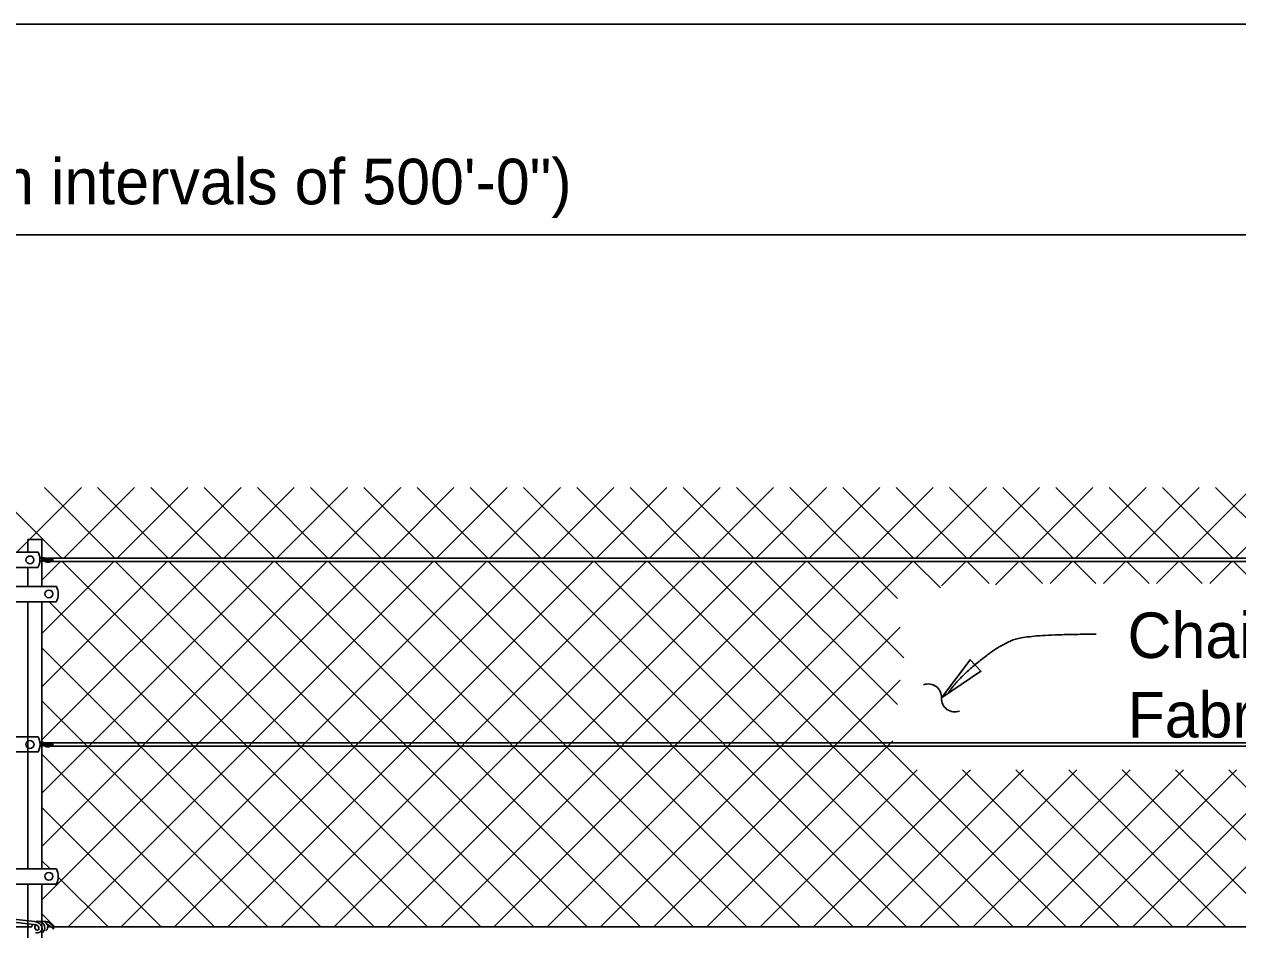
# Model space of a CAD drawing. Extents: x 0 to 41.1, y 0 to 26.4.
# Drawn here: x 12.4 to 17.77, y 22.39 to 26.4 of the extents above; entities that cross this region are included whole.
import ezdxf

# ---------------------------------------------------------------- set-up
doc = ezdxf.new("R2010")
doc.units = 0
for name, color, linetype in [('Dimension', 7, 'Continuous'), ('Miscellaneous', 7, 'Continuous'), ('Miscellaneous1', 7, 'Continuous'), ('SteelMisc', 7, 'Continuous'), ('TextStructures', 7, 'Continuous')]:
    doc.layers.add(name, color=color, linetype=linetype)

msp = doc.modelspace()

# ---------------------------------------------------------------- linework, layer by layer
at = {"layer": 'Dimension'}
msp.add_line((2.2062, 25.4682), (22.2062, 25.4682), dxfattribs=at)
msp.add_lwpolyline([(16.4595, 23.4182), (16.6347, 23.5361), (16.5861, 23.5872)], close=True, dxfattribs=at)
for centre, start, end in [((16.4004, 23.4201), 357.7178, 109.445), ((16.5195, 23.4153), 177.7178, 289.445)]:
    msp.add_arc(centre, 0.0596, start, end, dxfattribs=at)
msp.add_open_spline([(17.1447, 23.6998), (16.8545, 23.6998), (16.7179, 23.655), (16.5309, 23.5014), (16.4925, 23.4438)], degree=2, dxfattribs=at)
at = {"layer": 'Miscellaneous'}
for p, q in [((12.3656, 24.0631), (12.6516, 24.349)), ((12.4881, 24.349), (12.8006, 24.0365)), ((12.5748, 24.0365), (12.8873, 24.349)), ((12.7238, 24.349), (13.0364, 24.0365)), ((12.8105, 24.0365), (13.123, 24.349)), ((12.9595, 24.349), (13.2721, 24.0365)), ((13.0462, 24.0365), (13.3587, 24.349)), ((13.1952, 24.349), (13.5078, 24.0365)), ((13.2819, 24.0365), (13.5944, 24.349)), ((13.4309, 24.349), (13.7435, 24.0365)), ((13.5176, 24.0365), (13.8301, 24.349)), ((13.6666, 24.349), (13.9792, 24.0365)), ((13.7533, 24.0365), (14.0658, 24.349)), ((13.9023, 24.349), (14.2149, 24.0365)), ((13.989, 24.0365), (14.3015, 24.349)), ((14.138, 24.349), (14.4506, 24.0365)), ((14.2247, 24.0365), (14.5372, 24.349)), ((14.3737, 24.349), (14.6863, 24.0365)), ((14.4604, 24.0365), (14.7729, 24.349)), ((14.6094, 24.349), (14.922, 24.0365)), ((14.6961, 24.0365), (15.0086, 24.349)), ((14.8451, 24.349), (15.1577, 24.0365)), ((14.9318, 24.0365), (15.2443, 24.349)), ((15.0808, 24.349), (15.3934, 24.0365)), ((15.1675, 24.0365), (15.48, 24.349)), ((15.3165, 24.349), (15.6291, 24.0365)), ((15.4032, 24.0365), (15.7157, 24.349)), ((15.5522, 24.349), (15.8648, 24.0365)), ((15.6389, 24.0365), (15.9514, 24.349)), ((15.7879, 24.349), (16.1005, 24.0365)), ((15.8746, 24.0365), (16.1871, 24.349)), ((16.0236, 24.349), (16.3362, 24.0365)), ((16.1103, 24.0365), (16.4228, 24.349)), ((16.2593, 24.349), (16.5719, 24.0365)), ((16.346, 24.0365), (16.6585, 24.349)), ((16.4951, 24.349), (16.8076, 24.0365)), ((16.5817, 24.0365), (16.8942, 24.349)), ((16.7308, 24.349), (17.0433, 24.0365)), ((16.8174, 24.0365), (17.1299, 24.349)), ((16.9665, 24.349), (17.279, 24.0365)), ((17.0531, 24.0365), (17.3656, 24.349)), ((17.2022, 24.349), (17.5147, 24.0365)), ((17.2888, 24.0365), (17.6013, 24.349)), ((17.4379, 24.349), (17.7504, 24.0365)), ((17.5245, 24.0365), (17.837, 24.349)), ((17.6736, 24.349), (17.9861, 24.0365)), ((17.7602, 24.0365), (18.0727, 24.349)), ((12.352, 24.2494), (12.5649, 24.0365)), ((12.4771, 22.5246), (13.9742, 24.0218)), ((12.4771, 22.7603), (13.7385, 24.0218)), ((12.4771, 22.996), (13.5028, 24.0218)), ((12.4771, 23.2317), (13.2671, 24.0218)), ((12.4771, 23.4674), (13.0314, 24.0218)), ((12.4771, 23.7031), (12.7957, 24.0218)), ((12.4771, 23.9388), (12.56, 24.0218)), ((12.5669, 24.0218), (14.1839, 22.4048)), ((12.5929, 22.4048), (14.2099, 24.0218)), ((12.8026, 24.0218), (14.4196, 22.4048)), ((12.8286, 22.4048), (14.4456, 24.0218)), ((13.0383, 24.0218), (14.6553, 22.4048)), ((13.0643, 22.4048), (14.6813, 24.0218)), ((13.274, 24.0218), (14.891, 22.4048)), ((13.3, 22.4048), (14.917, 24.0218)), ((13.5097, 24.0218), (15.1267, 22.4048)), ((13.5357, 22.4048), (15.1527, 24.0218)), ((13.7454, 24.0218), (15.3624, 22.4048)), ((13.7714, 22.4048), (15.3884, 24.0218)), ((13.9811, 24.0218), (15.5981, 22.4048)), ((14.0071, 22.4048), (15.6241, 24.0218)), ((14.2168, 24.0218), (15.8338, 22.4048)), ((14.2428, 22.4048), (15.8598, 24.0218)), ((14.4525, 24.0218), (16.0695, 22.4048)), ((14.4785, 22.4048), (16.0955, 24.0218)), ((14.6882, 24.0218), (16.3052, 22.4048)), ((14.7142, 22.4048), (16.3312, 24.0218)), ((14.9239, 24.0218), (16.5409, 22.4048)), ((15.1596, 24.0218), (16.2441, 22.9373)), ((15.3953, 24.0218), (16.2441, 23.173)), ((15.631, 24.0218), (16.2647, 23.3881)), ((15.8667, 24.0218), (16.293, 23.5955)), ((16.1024, 24.0218), (16.2656, 23.8586)), ((16.3381, 24.0218), (16.4551, 23.9048)), ((16.4597, 23.9145), (16.5669, 24.0218)), ((16.5738, 24.0218), (16.6715, 23.9241)), ((16.699, 23.9181), (16.8026, 24.0218)), ((16.8095, 24.0218), (16.9072, 23.9241)), ((16.9407, 23.9241), (17.0384, 24.0218)), ((17.0452, 24.0218), (17.1429, 23.9241)), ((17.1764, 23.9241), (17.2741, 24.0218)), ((17.281, 24.0218), (17.3786, 23.9241)), ((17.4121, 23.9241), (17.5098, 24.0218)), ((17.5167, 24.0218), (17.6143, 23.9241)), ((17.6478, 23.9241), (17.7455, 24.0218)), ((17.7524, 24.0218), (17.85, 23.9241)), ((12.5096, 23.8433), (13.9482, 22.4048)), ((14.9499, 22.4048), (16.2763, 23.7311)), ((12.4771, 23.6402), (13.7125, 22.4048)), ((15.1856, 22.4048), (16.2774, 23.4965)), ((12.4771, 23.4045), (13.4768, 22.4048)), ((15.4214, 22.4048), (16.2441, 23.2275)), ((12.4771, 23.1688), (13.2411, 22.4048)), ((16.2441, 23.173), (17.0123, 22.4048)), ((15.6571, 22.4048), (16.3522, 23.0999)), ((15.8928, 22.4048), (16.5879, 23.0999)), ((16.1285, 22.4048), (16.8236, 23.0999)), ((16.3642, 22.4048), (17.0593, 23.0999)), ((16.5529, 23.0999), (17.248, 22.4048)), ((16.5999, 22.4048), (17.295, 23.0999)), ((16.7886, 23.0999), (17.4837, 22.4048)), ((16.8356, 22.4048), (17.5307, 23.0999)), ((17.0243, 23.0999), (17.7194, 22.4048)), ((17.0713, 22.4048), (17.7664, 23.0999)), ((17.26, 23.0999), (17.9551, 22.4048)), ((17.307, 22.4048), (18.0021, 23.0999)), ((17.4957, 23.0999), (18.1908, 22.4048)), ((17.5427, 22.4048), (18.2378, 23.0999)), ((17.7314, 23.0999), (18.4265, 22.4048)), ((12.4771, 22.9331), (13.0054, 22.4048)), ((16.2441, 22.9373), (16.7766, 22.4048)), ((12.4771, 22.6974), (12.5135, 22.6609)), ((12.5496, 22.6249), (12.7697, 22.4048)), ((12.4771, 22.4617), (12.534, 22.4048))]:
    msp.add_line(p, q, dxfattribs=at)
at = {"layer": 'Miscellaneous1'}
msp.add_lwpolyline([(0, 26.4), (41.0667, 26.4), (41.0667, 0), (0, 0)], close=True, dxfattribs=at)
at = {"layer": 'SteelMisc'}
for p, q in [((12.4145, 24.0636), (12.4145, 24.1198)), ((12.4145, 24.1198), (12.477, 24.1198)), ((12.477, 24.0396), (12.477, 24.1198)), ((12.0505, 24.0637), (12.4602, 24.0637)), ((12.4675, 24.0412), (12.4967, 24.0366)), ((12.4676, 24.0412), (12.4968, 24.0366)), ((12.468, 24.0207), (12.5016, 24.0264)), ((12.4681, 24.0362), (12.4941, 24.0321)), ((12.4681, 24.0207), (12.5017, 24.0264)), ((12.4682, 24.0362), (12.4942, 24.0321)), ((12.4684, 24.0255), (12.4983, 24.0304)), ((12.4685, 24.0255), (12.4984, 24.0304)), ((12.477, 24.0347), (12.477, 24.0269)), ((12.4771, 24.0396), (12.4771, 23.9109)), ((12.5051, 24.0365), (21.8852, 24.0365)), ((12.5051, 24.0218), (21.9118, 24.0218)), ((12.0505, 23.9959), (12.4598, 23.9959)), ((12.4146, 23.9959), (12.4146, 23.9109)), ((12.0505, 23.9109), (12.5416, 23.9109)), ((12.0505, 23.8433), (12.5408, 23.8433)), ((12.4146, 23.8433), (12.4146, 22.6609)), ((12.4771, 23.8433), (12.4771, 22.6609)), ((12.0506, 23.2462), (12.4603, 23.2462)), ((12.4676, 23.2237), (12.4969, 23.2191)), ((12.4677, 23.2237), (12.497, 23.2191)), ((12.4683, 23.2187), (12.4943, 23.2146)), ((12.4684, 23.2187), (12.4944, 23.2146)), ((12.4686, 23.2081), (12.4985, 23.213)), ((12.4687, 23.2081), (12.4986, 23.213)), ((12.4772, 23.2172), (12.4772, 23.2094)), ((12.5053, 23.219), (21.8854, 23.219)), ((12.0506, 23.1785), (12.46, 23.1785)), ((12.4681, 23.2033), (12.5018, 23.2089)), ((12.4683, 23.2033), (12.5019, 23.2089)), ((12.5053, 23.2043), (21.912, 23.2043)), ((12.0505, 22.6609), (12.5416, 22.6609)), ((12.0505, 22.5933), (12.5408, 22.5933)), ((12.4146, 21.4109), (12.4146, 22.5933)), ((12.4771, 21.4109), (12.4771, 22.5933)), ((12.3515, 22.4391), (12.4435, 22.4275)), ((12.3515, 22.4245), (12.4434, 22.415)), ((12.352, 22.4048), (12.4324, 22.4048)), ((12.5028, 22.4048), (12.518, 22.4048)), ((12.5265, 22.4048), (21.8852, 22.4048))]:
    msp.add_line(p, q, dxfattribs=at)
for centre, major_axis in [((12.4241, 24.0291), (-0.0178, 0)), ((12.5079, 23.8782), (-0.0177, 0)), ((12.4243, 23.2117), (-0.0178, 0)), ((12.5079, 22.6282), (-0.0177, 0))]:
    msp.add_ellipse(centre, major_axis=major_axis, ratio=0.957868, dxfattribs=at)
for centre, major_axis, ratio, start_param, end_param in [((12.3908, 24.03), (0.0776, 0), 0.957868, 5.803915, 6.752041), ((12.4993, 24.0267), (-0.0095, 0), 0.957868, 5.673972, 6.052579), ((12.4993, 24.0267), (-0.0095, 0), 0.957868, 0.252467, 1.271421), ((12.4934, 24.0225), (0.00982, 0), 0.957868, 0.655696, 1.505671), ((12.4953, 24.0274), (0.0115, -0.0041), 0.737732, 5.08821, 8.212701), ((12.4987, 24.025), (0.00301, 0), 0.957868, 3.28349, 5.170635), ((12.4993, 24.0272), (-0.00453, 0), 0.957868, 5.149727, 5.551998), ((12.4966, 24.0259), (0.00527, 0), 0.957868, 5.058829, 7.342751), ((12.501, 24.0283), (-0.00872, 0), 0.957868, 2.1008, 4.992926), ((12.4987, 24.025), (0.00301, 0), 0.957868, 0.004594, 0.141897), ((12.5071, 24.0278), (0.00944, 0), 0.957868, 4.316497, 6.557353), ((12.5075, 24.0288), (-0.00872, 0), 0.957868, 3.323334, 4.992926), ((12.5075, 24.0288), (-0.00503, 0), 0.92697, 1.780895, 4.712389), ((12.5122, 24.0233), (-0.0142, 0), 0.957868, 3.141593, 4.79635), ((12.5042, 24.0082), (0.0274, 0), 0.957868, 0.628521, 1.149654), ((12.472, 23.8778), (0.0776, 0), 0.957868, 5.801244, 6.745158), ((12.391, 23.2125), (0.0776, 0), 0.957868, 5.803915, 6.752041), ((12.4994, 23.2092), (-0.0095, 0), 0.957868, 5.673972, 6.052579), ((12.4936, 23.205), (0.00982, 0), 0.957868, 0.655696, 1.505671), ((12.4955, 23.2099), (0.0115, -0.0041), 0.737732, 5.08821, 8.212701), ((12.4995, 23.2097), (-0.00453, 0), 0.957868, 5.149727, 5.551998), ((12.4967, 23.2084), (0.00527, 0), 0.957868, 5.058829, 7.342751), ((12.5011, 23.2108), (-0.00872, 0), 0.957868, 2.1008, 4.992926), ((12.5073, 23.2104), (0.00944, 0), 0.957868, 4.316497, 6.557353), ((12.5077, 23.2113), (-0.00872, 0), 0.957868, 3.323334, 4.992926), ((12.5077, 23.2113), (-0.00503, 0), 0.92697, 1.780895, 4.712389), ((12.5124, 23.2058), (-0.0142, 0), 0.957868, 3.141593, 4.79635), ((12.5044, 23.1908), (0.0274, 0), 0.957868, 0.628521, 1.149654), ((12.4994, 23.2092), (-0.0095, 0), 0.957868, 0.252467, 1.271421), ((12.4989, 23.2075), (0.00301, 0), 0.957868, 3.28349, 5.170635), ((12.4989, 23.2075), (0.00301, 0), 0.957868, 0.004594, 0.141897), ((12.472, 22.6278), (0.0776, 0), 0.957868, 5.801244, 6.745158), ((12.4572, 22.4013), (-0.0251, 0), 0.957868, 5.640694, 6.136824), ((12.4417, 22.3902), (0.0259, 0), 0.957868, 0.636815, 1.505671), ((12.4468, 22.4032), (0.0303, -0.0108), 0.724765, 0.058937, 1.929515), ((12.4574, 22.4025), (-0.0119, 0), 0.957868, 5.149694, 6.840495), ((12.4603, 22.4014), (-0.0295, 0), 0.957868, 2.287002, 5.15055), ((12.4501, 22.3991), (0.0139, 0), 0.957868, 6.080589, 6.743456), ((12.479, 22.4067), (-0.023, 0), 0.957868, 3.422131, 5.0491), ((12.4915, 22.3923), (-0.0373, 0), 0.957868, 3.175144, 4.855322), ((12.4779, 22.4042), (0.0249, 0), 0.957868, 5.476514, 6.65252), ((12.4704, 22.3526), (0.0724, 0), 0.957868, 0.631079, 1.150052), ((12.4574, 22.4025), (-0.0119, 0), 0.957868, 0.560069, 0.643501), ((12.4558, 22.3967), (0.00795, 0), 0.957868, 3.283494, 6.243757), ((12.4569, 22.3945), (-0.0206, -0.0021), 0.798607, 1.063032, 2.96375)]:
    msp.add_ellipse(centre, major_axis=major_axis, ratio=ratio, start_param=start_param, end_param=end_param, dxfattribs=at)

# ---------------------------------------------------------------- texts
at = {"layer": 'Dimension'}
for s, p in [('Chain Link ', (17.2835, 23.5945)), ('Fabric ', (17.2835, 23.2425))]:
    msp.add_text(s, height=0.2016, dxfattribs=at).set_placement(p)
at = {"layer": 'TextStructures'}
msp.add_text('Pull Post Assembly (required at maximum intervals of 500\'-0")', height=0.2016, dxfattribs=at).set_placement((7.4383, 25.603))

doc.saveas('drawing.dxf')
